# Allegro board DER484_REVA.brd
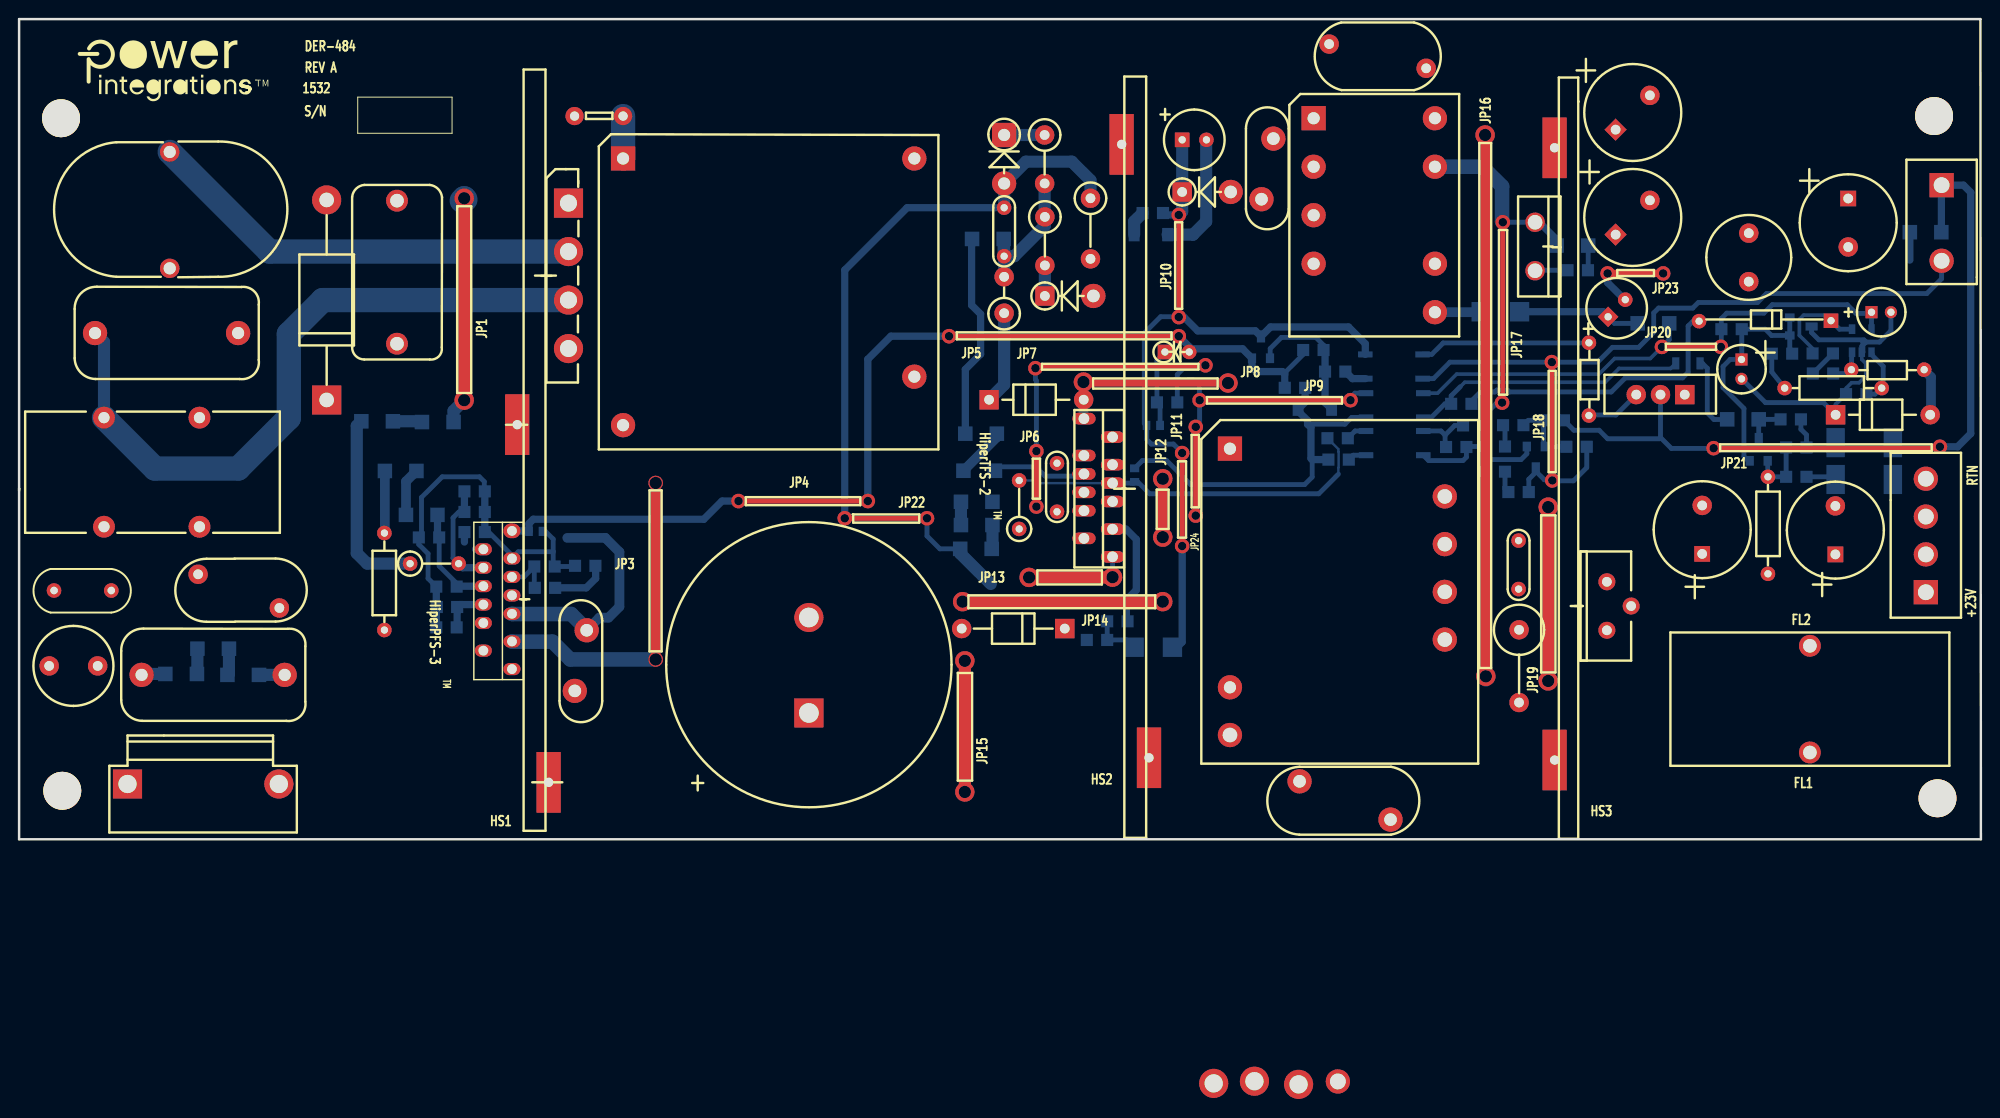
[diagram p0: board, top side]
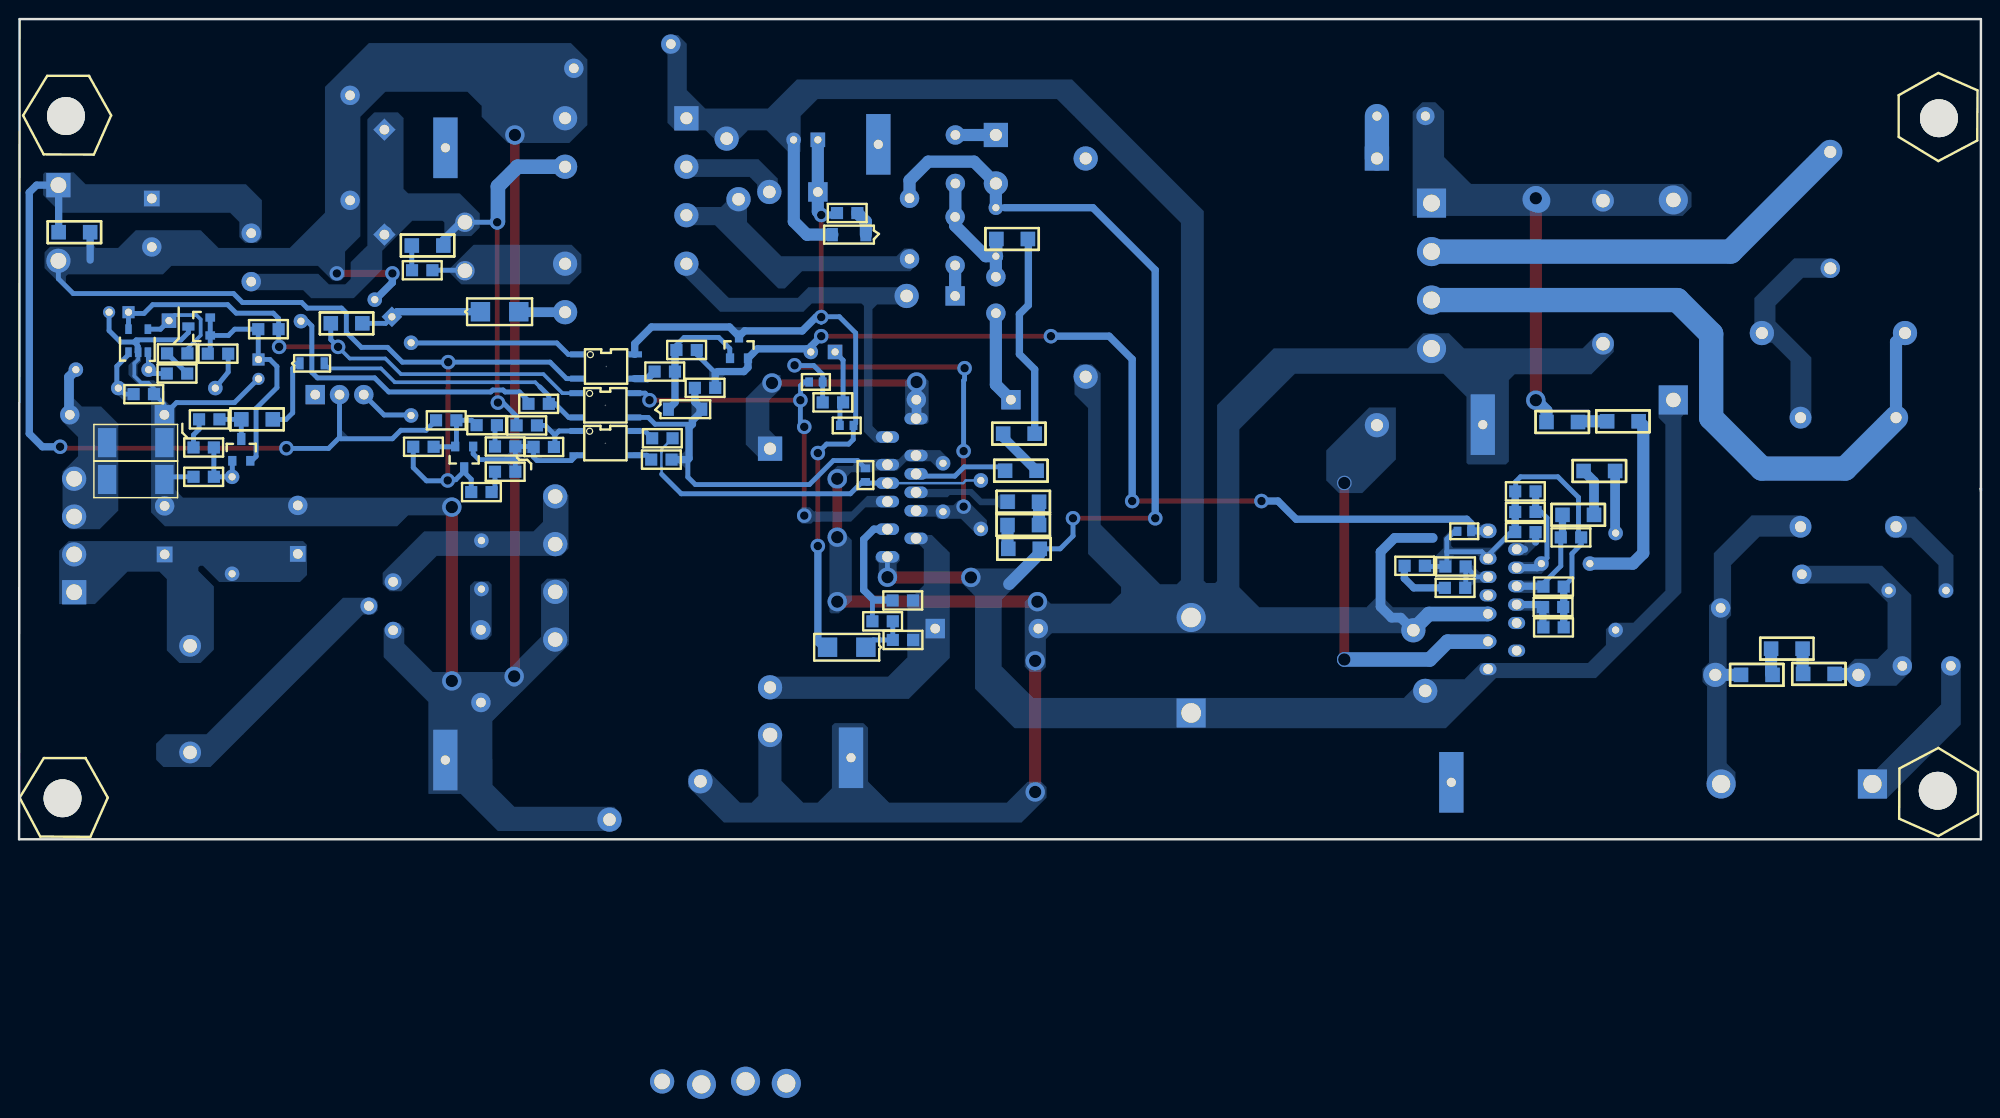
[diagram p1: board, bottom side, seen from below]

Outline 205.44 x 85.93 mm; copper layers: TOP, BOTTOM. Coordinates in mm from the lower left corner of the outline.
Outline path: 0,36.5 0,85.93 205.38,85.93 205.44,0 0,0 0,36.73 0.03,36.73

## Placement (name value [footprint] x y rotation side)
BR1  GBU8K-BP  [PIDAXBRIDGEGBU8]  57.53 66.65 270 top
C1  330 nF  [PINPCAPRAD760X380590050]  12.83 17.22 0 top
C2  330 nF  [PINPCAPRAD760X380590050]  7.95 53.04 0 top
C3  1.0 uF  [PI_NP_CAP_RAD715X370LS590D050]  39.57 66.9 270 top
C4  1 uF  [PISMC0603]  53.39 32.26 0 bottom
C5  1 uF  [PISMC0805]  46.63 32.18 0 bottom
C6  470 pF  [PISMC0805]  46.63 34.29 0 bottom
C7  100 nF  [PISMC0805]  53.95 28.58 0 bottom
C8  1 uF  [PISMC0805]  60.35 28.65 180 bottom
C9  1 nF  [PISMC0805]  45.82 22.2 180 bottom
C10  10 nF  [PINPCAPRAD500X180250040]  58.17 15.54 90 top
C11  470 pF  [PISMC0805]  45.82 26.47 180 bottom
C12  220 uF  [PI_POLCAP_CLY_1181LS400D081]  82.7 13.23 90 top
C13  10 nf  [PISMC0805]  134.67 47.29 180 bottom
C14  2.2 nF  [PINPCAPRAD200X100200030]  103.15 61.09 90 top
C15  100 nF  [PISMC0805]  113.97 25.02 180 bottom
C16  100 nF  [PISMC0805]  113.94 20.88 180 bottom
C17  1.0  uF  [PINPCAPRAD200X100200030]  108.69 34.32 90 top
C18  220pF  [PISMC0603]  116.81 37.44 90 bottom
C19  220 pF  [PINPCAPRAD250X100200030]  157.02 31.29 270 top
C20  150 uF  [PIPOLCAPCYLD400LS200040]  190.2 29.85 90 top
C21  150 uF  [PIPOLCAPCYLD400LS200040]  176.25 29.9 90 top
C22  470 nF  [PISMC0805]  187.17 41.05 180 bottom
C23  10 uF  [PIPOLCAPCLYD200LS80030]  180.37 50.27 270 top
C24  68 nF  [PISMC0805]  187.83 48.79 0 bottom
C25  10 uF  [PIPOLCAPCLYD200LS80030]  193.98 55.22 0 bottom
C26  4.7 nF  [PINPCAPRAD640X260375040]  134.09 6.1 0 top
C27  10 nF  [PINPCAPRAD500X180250040]  131.37 73.41 270 top
C28  100 uF  [PIPOLCAPCYLD250LS100030]  121.79 73.28 0 top
C29  1 nF  [PINPYCAPRAD540X290LS400040]  137.19 83.31 0 top
C30  2.2 nF  [PISMC0805]  162.15 59.61 0 bottom
C31  100 uF  [PIPOLCAPCYLD250LS100030]  166.4 54.74 45 top
C32  1200 uF  [PIPOLCAPCYLD400LS200040]  167.18 74.35 45 top
C33  1200 uF  [PIPOLCAPCYLD400LS200040]  167.18 63.35 45 top
C34  2.2 uF  [PISMC0805]  155.6 38.51 180 bottom
C35  330 nF  [PISMC0805]  155.4 43.38 0 bottom
C36  330 uF  [PIPOLCAPCYLD400LS200040]  191.54 67.13 270 top
C37  1 uF  [PISMC1206]  201.29 63.6 180 bottom
D1  1N5408-T  [PIDV300X200X060DO15D0201AD]  32.21 46.02 90 top
D2  1N4148  [PIDAX375X070030DO35#2]  119.99 51.05 0 top
D3  1N4007  [PIDV200X110X040DO41]  107.42 56.92 0 top
D4  1N4007  [PIDAX475X125040DO41]  101.57 46.05 0 top
D5  US1J  [PISMDSMA]  116.76 20.12 0 bottom
D6  UF4005  [PIDAX475X125040DO41#2]  109.5 22.07 180 top
D7  UF4003  [PIDV200X110X040DO41]  121.79 67.82 0 top
D8  STTH2003CT  [PIDVTO2203]  166.27 24.43 90 top
D9  BAV19WS  [PISMSOD323]  176.02 49.86 180 bottom
D10  1N4148  [PIDAX375X070030DO35]  186.39 54.48 180 top
D11  1N4002-E3/54  [PIDV200X110X040DO41#2]  190.22 44.48 0 top
D12  MBR1045  [PIDVT0220ACREVA]  158.75 59.56 90 top
D13  US1J  [PISMDSMA]  157.12 55.27 180 bottom
F1  5 A  [PI_TR5_SUBMIN_FUSE]  3.15 18.16 0 top
HS1  HEATSINK, W/ ZIERICK, PI CUST  [PI_HS_DER484_BRIDGE]  55.12 80.65 0 top
HS2  HEATSINK, W/ ZIERICK, PI CUST  [PI_HS_DER484_ESIP]  115.75 79.91 270 top
HS3  HEATSINK, W/ ZIERICK, PI CUST  [PI_HS_DER484_DIODES]  161.06 0.05 90 top
J1  CON5  [PI_HDR_5PIN]  11.35 5.79 270 top
J2  CON4  [PI_HDR_4PIN]  199.67 25.88 0 top
J3  CON3  [PI_HDR_3PIN]  201.32 68.53 180 top
JP2  J  [PI_JUMPER200]  58.17 75.77 0 top
L1  9 mH  [PI_IND_4P_500X1050LS450D46_R1]  8.89 32.74 90 top
L2  330 uH  [PI_TOROID_2P_550X950_LS480_D050]  15.77 59.82 90 top
L3  221 uH  [PI_BOBBIN_BPQ32_20_DER484]  63.25 71.32 0 top
L4  880 uH  [PI_IND_2P_TOROIDAL]  187.53 14.68 90 top
L5  2.2 Uh  [PI_CHOKE_COILCRAFT_RFB0807]  181.13 58.42 90 top
NOREF  -  []  -181.41 -162.18 0 top
NOREF#2  -  []  -103.59 36.84 0 top
NOREF#3  -  []  205.44 0 90 top
NOREF#4  -  []  6.15 83.74 0 top
NOREF#5  -  []  0.03 0.03 0 top
POST1  Post Hex, 6-32, snap, 0.375L, NYL  [PIMTGHOLED156]  4.52 5.08 270 bottom
POST2  Post Hex, 6-32, snap, 0.375L, NYL  [PIMTGHOLED156]  200.53 75.77 180 bottom
POST3  Post Hex, 6-32, snap, 0.375L, NYL  [PIMTGHOLED156]  200.89 4.29 180 bottom
POST4  Post Hex, 6-32, snap, 0.375L, NYL  [PIMTGHOLED156]  4.39 75.54 90 bottom
Q1  MMBT4401LT1G  [PISMSOT23123_1]  129.11 50.39 180 bottom
Q2  MMBT4401LT1G  [PISMSOT23123_1]  181.23 39.65 180 bottom
R1  680 k  [PISMR1206]  15.32 17.32 0 bottom
R2  680 k  [PISMR1206]  18.67 19.96 0 bottom
R3  680 k  [PISMR1206]  21.82 17.22 0 bottom
R4  6.2 M  [PISMR1206]  45.49 43.71 180 bottom
R5  6.2 M  [PISMR1206]  39.14 43.79 180 bottom
R6  3.74 M  [PI14WVRESD100LS100D030#2]  40.94 28.88 0 top
R7  162 k  [PISMR0805]  46.63 36.45 0 bottom
R8  30.1 k  [PISMR0805]  54 26.34 0 bottom
R9  332 k  [PISMR0805]  45.87 24.33 180 bottom
R10  3.74 M  [PI14WVRESD100LS100D030]  38.25 21.92 90 top
R11  6.2 M  [PISMR1206]  38.3 38.58 0 bottom
R12  6.2 M  [PISMR1206]  40.51 33.99 0 bottom
R13  162 k  [PISMR0805]  43.99 31.62 180 bottom
R14  4.7 k  [PISMR0805]  136.75 49 0 bottom
R15  4.7 k  [PISMR0805]  134.47 51.26 0 bottom
R16  7.5 k  [PISMR0603]  119.48 43.36 180 bottom
R17  1.33 M  [PISMR1206]  103.1 62.89 180 bottom
R18  1.33 M  [PISMR1206]  99.09 42.49 0 bottom
R19  620  [PISMR0805]  121.29 45.77 180 bottom
R20  1.33 M  [PISMR1206]  102.18 38.61 180 bottom
R21  232 k  [PISMR0603]  121.29 47.9 0 bottom
R22  1.33 M  [PISMR1206]  101.85 30.43 180 bottom
R23  1.33 M  [PISMR1206]  101.93 32.92 180 bottom
R24  1.33 M  [PISMR1206]  101.93 35.36 180 bottom
R25  100  [PI12WVRESD180LS150D040#2]  107.39 73.79 270 top
R26  4.7  [PI12WVRESD180LS150D040#2]  107.42 65.2 270 top
R27  2.2  [PI12WVRESD180LS150D040]  103.15 58.93 270 top
R28  2 k  [PISMR0805]  116.08 22.83 180 bottom
R29  107 k  [PI14WVRESD100LS200D030]  104.72 32.51 90 top
R30  0.0  [PISMR0805]  137.01 42.01 0 bottom
R31  0.0  [PISMR0805]  139.24 39.78 180 bottom
R32  15  [PI2WVRESD200LS300D040]  157.07 21.95 270 top
R33  2.2 k  [PISMR0805]  149.96 45.62 0 bottom
R34  3.3 k  [PISMR0805]  187.81 50.9 0 bottom
R35  1.5 k  [PISMR1206]  182.17 43.99 180 bottom
R36  3.3 k  [PISMR0805]  178.26 53.44 0 bottom
R37  97.6 k  [PISMR0805]  185.67 50.88 180 bottom
R38  1.1 k  [PI14WRESD100LS400D030]  184.89 47.27 0 top
R39  10.2 k  [PISMR0805]  193.45 46.63 180 bottom
R40  100  [PISMR0805]  184.45 43.99 0 bottom
R41  93.1 k  [PI14WRESD100LS400D030]  183.13 37.97 270 top
R42  4.99 k  [PISMR0805]  185.04 37.97 0 bottom
R43  10 k  [PI18WRESD080LS300D030]  191.87 49.2 0 top
R44  0.1  [PISMR2512]  190.22 37.69 0 bottom
R45  220  [PISMR1206]  169.49 54.05 0 bottom
R46  0.1  [PISMR2512]  190.22 41.55 0 bottom
R47  2.2  [PI12WVRESD180LS150D040#3]  112.19 67.16 270 top
R48  1 k  [PISMR0805]  117.65 65.61 0 bottom
R49  10  [PISMR1206]  161.01 62.2 0 bottom
R50  1 k  [PISMR0805]  149.43 41.1 0 bottom
R51  680  [PISMR0805]  155.96 36.37 0 bottom
R52  100  [PISMR0805]  151.21 43.36 0 bottom
R53  1 k  [PISMR0805]  153.47 41.15 0 bottom
R54  4.99 k  [PISMR0805]  161.77 43.89 180 bottom
R55  4.99 k  [PISMR0805]  162.03 41.12 0 bottom
R56  4.7 k  [PI18WVRESD80LS100D030]  164.39 44.4 90 top
RT1  2.5  [PI_RAD180X395LS235D031]  9.65 26.06 180 top
RV1  320 Vac  [PIDISC500X225LS335X140040]  18.75 27.76 0 top
SW1  SPDT SLIDE  [PI_SWITCH_SPDT_SLIDE_PCBM_1]  174.42 46.58 90 top
T1  EER35  [PI_BOBBIN_EER35_14P_DER484]  126.8 40.92 0 top
T2  EF25  [PI_BOBBIN_EF25_10P_DER484]  135.56 75.54 0 top
U1  PFS7528H  [PI_IC_EESIP_SOCKET]  51.61 32.31 270 top
U2  PC357A  [PI_4_SMD]  143.97 49.53 270 bottom
U3  TFS-7706H  [PI_IC_ESIP16-12_OVAL_SLOT_RECPT]  114.5 44.07 270 top
U4  PC357A  [PI_4_SMD]  144.04 45.47 270 bottom
U5  LM431BIM3/NOPB  [PISMSOT23123]  185.42 54.66 90 bottom
U6  LM321  [PISMSOT235]  193.98 51.03 180 bottom
U7  PC357A  [PI_4_SMD]  144.04 41.5 270 bottom
U8  LM431AIM3  [PISMSOT23123]  159.77 41.15 0 bottom
VR1  P6KE150A  [PIDV200X140X050DO15DO204AC]  103.15 73.79 270 top
VR2  MMSZ5243BT1G  [PI_SM_SOD-123_12]  137.44 45.06 180 bottom
VR3  MMSZ5248B-7-F  [PI_SM_SOD-123_12]  116.76 63.35 0 bottom

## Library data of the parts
BR1 = DISCRETE BRIDGE_+~~-: alternate symbols: (pidaxbridgegbu8_horz)
C1-C11 C13-C19 C22 C24 C26 C27 C30 C34 C35 C37 = CAP NP
C12 C20 C21 C32 C33 = CAP POL
C23 C25 = CAP POL: alternate symbols: (pipolcapclyd200ls80030h)
C28 = CAP POL: alternate symbols: (pipolcapclyd250ls100d30h590); tolerance: 20
C29 = CAP NP: alternate symbols: (pinpycaprad540x290ls400040h)
C31 = CAP POL: alternate symbols: (pipolcapclyd250ls100d30h590)
C36 = CAP POL: alternate symbols: (pipolcapclyd400x530ls200030h)
D1 = DIODE: alternate symbols: (pidax800x225060do15do201ad,pidv300x200x060do14wbead)
D2 D10 = DIODE: alternate symbols: (pidax375x070030do35,pidv100x080x030do35)
D3 D4 D7 D11 = DIODE: alternate symbols: (pidax475x125040do41,pidv200x110x040do41wbead,pidax390x125040do41)
D5 D9 D13 = DIODE
D6 = DIODE: alternate symbols: (pidax475x125040do41,pidax390x125040do41)
D8 = D_DUAL_CK_ACA_4: alternate symbols: (pidvto2203vf1)
D12 = DIODE SCHOTTKY
F1 = FUSE
HS1-HS3 = HS-PI_CUSTOM2
J1 = CON5
J2 = CON4
J3 = CON3
JP2 = JUMPER_1
L1 = INDUCTOR_4P_revB: alternate symbols: (pi_ind_4p_500x1050ls450d46_r1)
L2 L5 = INDUCTOR
L3 = INDUCTOR_DER484_PFC
L4 = INDUCTOR_DER484
POST1-POST4 = POST_CRKT_BRD_6-32_HEX
Q1 Q2 = NPN_BEC
R1-R5 R7-R9 R11-R22 R28 R30 R31 R33-R37 R39 R40 R42 R44-R46 R48-R55 = R
R6 R10 R29 R38 R41 = R: alternate symbols: (pi14wvresd100ls200d030,pi14wresd100ls400d030,pi14wresd100ls500d030)
R23 R24 = R: tolerance: 1%
R25-R27 R47 = R: alternate symbols: (pi12wvresd180ls200d040,pi12wvresd180ls250d040,pi12wresd180ls675d040)
R32 = R: alternate symbols: (pi2wresd200ls900d040,pi2wvresd200ls300d040,pi2wvresd200ls400d040)
R43 = R: alternate symbols: (pi18wresd080ls300d030); tolerance: 1%
R56 = R: alternate symbols: (pi18wresd080ls300d030)
RT1 = THERMISTOR: alternate symbols: (pirad550x410ls300040_h)
RV1 = VARISTOR: alternate symbols: (pi_rad450x550ls300d040_h)
SW1 = SW SLIDE-SPDT
T1 = BEER35_CUSTOM_DER484
T2 = BEF25_CUSTOM_DER484
U1 = DEV_HIPERPFS-3-eSIP-16C: alternate symbols: (pi_ic_esip16-13_socket_hpii ,pi_ic_esip16-13_oval_hpii,pi_ic_eesip_socket)
U2 U4 U7 = OPTO_A_B
U3 = HiperTFS_II_I_2_ROW: alternate symbols: (pi_ic_esip16-12_oval_slot_recpt)
U5 U8 = TL431/SOT-23_CAR
U6 = LM321_SOT23-5
VR1 = DIODE_ZENER: alternate symbols: (pidax550x140050do15do204ac)
VR2 VR3 = DIODE_ZENER

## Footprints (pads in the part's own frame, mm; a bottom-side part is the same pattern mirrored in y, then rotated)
PI2WVRESD200LS300D040
  round 2.032 hole 1.016: 1(0,0) 2(7.62,0)
PI12WVRESD180LS150D040
  round 2.032 hole 1.016: 1(0,0) 2(3.81,0)
PI12WVRESD180LS150D040#2
  round 2.032 hole 1.016: 1(0,0) 2(5.08,0)
PI12WVRESD180LS150D040#3
  round 2.032 hole 1.016: 1(0,0) 2(6.35,0)
PI14WRESD100LS400D030
  round 1.524 hole 0.762: 1(0,0) 2(10.16,0)
PI14WVRESD100LS100D030
  round 1.524 hole 0.762: 1(0,0) 2(10.16,0)
PI14WVRESD100LS100D030#2
  round 1.524 hole 0.762: 1(0,0) 2(5.08,0)
PI14WVRESD100LS200D030
  round 1.524 hole 0.762: 1(0,0) 2(5.08,0)
PI18WRESD080LS300D030
  round 1.524 hole 0.762: 1(0,0) 2(7.62,0)
PI18WVRESD80LS100D030
  round 1.524 hole 0.762: 1(0,0) 2(7.62,0)
PI_4_SMD
  rect 0.635x1.524 smd: 1(-1.27,-2.997) 2(1.27,-2.997) 3(1.27,2.997) 4(-1.27,2.997)
PI_BOBBIN_BPQ32_20_DER484
  round 2.54 hole 1.27: (30.5,0) 6(0,-27.94) 8(30.5,-22.86)
  rect 2.54x2.54 hole 1.27: 1(0,0)
PI_BOBBIN_EER35_14P_DER484
  rect 2.54x2.54 hole 1.27: 1(0,0)
  round 2.54 hole 1.27: 6(0,-25.001)
  round 2.54 hole 1.524: 7(0,-30) 10(22.499,-20) 11(22.499,-15.001) 12(22.499,-10) 13(22.499,-5.001)
PI_BOBBIN_EF25_10P_DER484
  rect 2.54x2.54 hole 1.27: 1(0,0)
  round 2.54 hole 1.27: 2(0,-5.08) 3(0,-10.16) 4(0,-15.24) 6(12.7,-20.32) 7(12.7,-15.24) 9(12.7,-5.08) 10(12.7,0)
PI_CHOKE_COILCRAFT_RFB0807
  round 2.032 hole 1.016: 1(0,0) 2(5.08,0)
PI_HDR_3PIN
  rect 2.54x2.54 hole 1.651: 1(0,0)
  round 2.54 hole 1.651: 2(63.221,93.904) 3(0,7.925)
PI_HDR_4PIN
  rect 2.54x2.54 hole 1.651: 1(0,0)
  round 2.54 hole 1.651: 2(0,3.962) 3(0,7.925) 4(0,11.887)
PI_HDR_5PIN
  rect 3.048x3.048 hole 1.905: 1(0,0)
  round 3.048 hole 1.905: 2(31.369,113.741) 3(31.14,118.008) 4(31.471,122.631) 5(0,15.85)
PI_HS_DER484_BRIDGE
  rect 2.54x6.35 hole 0.965: 1(-2.957,-37.208) 2(0.338,-74.681)
PI_HS_DER484_DIODES
  rect 6.35x2.54 hole 0.965: 1(8.247,0.259) 2(72.393,0.272)
PI_HS_DER484_ESIP
  rect 6.35x2.54 hole 0.965: 1(71.369,2.57) 2(7.104,-0.287)
PI_IC_EESIP_SOCKET
  oval 1.524x1.778 hole 1.016: 1(0,0)
  oval 1.27x1.778 hole 1.016: 3(1.93,-2.997) 4(2.896,0) 5(3.861,-2.997) 6(4.826,0) 7(5.791,-2.997) 8(6.756,0) 9(7.722,-2.997) 10(8.687,0) 11(9.652,-2.997) 13(11.582,0) 14(12.548,-2.997) 16(14.478,0)
PI_IC_ESIP16-12_OVAL_SLOT_RECPT
  oval 1.219x2.438 hole 1.118: 1(0,-2.997) 3(1.93,0) 5(3.861,-2.997) 6(4.826,0) 7(5.791,-2.997) 8(6.756,0) 9(7.722,-2.997) 10(8.687,0) 11(9.652,-2.997) 13(11.582,0) 14(12.548,-2.997) 16(14.478,0)
PI_IND_2P_TOROIDAL
  round 2.286 hole 1.422: 1(-5.588,0) 2(5.588,0)
PI_IND_4P_500X1050LS450D46_R1
  round 2.286 hole 1.168: 1(0,-10) 2(11.43,-10) 3(0,0) 4(11.43,0)
PI_JUMPER200
  round 1.905 hole 0.965: 1(0,0) 2(5.08,0)
PI_NP_CAP_RAD715X370LS590D050
  round 2.286 hole 1.422: 1(0,0) 2(14.986,0)
PI_POLCAP_CLY_1181LS400D081
  rect 3.048x3.048 hole 2.057: 1(0,0)
  round 3.048 hole 2.057: 2(10,0)
PI_RAD180X395LS235D031
  round 1.524 hole 0.787: 1(0,0) 2(5.994,0)
PI_SM_SOD-123_12
  rect 1.143x1.397 smd: 1(0,0) 2(3.505,0)
PI_SWITCH_SPDT_SLIDE_PCBM_1
  rect 2.032x2.032 hole 1.016: 1(0,0)
  round 2.032 hole 1.016: 2(0,2.54) 3(0,5.08)
PI_TOROID_2P_550X950_LS480_D050
  round 2.032 hole 1.27: 1(0,0) 2(12.192,0)
PI_TR5_SUBMIN_FUSE
  round 2.032 hole 1.016: 1(0,0) 2(5.08,0)
PIDAX375X070030DO35
  rect 1.524x1.524 hole 0.762: 1(-3.353,0.152)
  round 1.524 hole 0.762: 2(10.465,0.203)
PIDAX375X070030DO35#2
  rect 1.524x1.524 hole 0.762: 1(0,0)
  round 1.524 hole 0.762: 2(2.54,0)
PIDAX475X125040DO41
  rect 2.032x2.032 hole 1.016: 1(0,0)
  round 2.032 hole 1.016: 2(9.906,0)
PIDAX475X125040DO41#2
  rect 2.032x2.032 hole 1.016: 1(0,0)
  round 2.032 hole 1.016: 2(10.795,0)
PIDAXBRIDGEGBU8
  rect 3.048x3.048 hole 1.778: 1(0,0)
  round 3.048 hole 1.778: 2(5.08,0) 3(10.16,0) 4(15.24,0)
PIDISC500X225LS335X140040
  round 2.032 hole 1.016: 1(0,0) 2(8.509,-3.531)
PIDV200X110X040DO41
  rect 2.032x2.032 hole 1.016: 1(0,0)
  round 2.54 hole 1.321: 2(5.08,0)
PIDV200X110X040DO41#2
  rect 2.032x2.032 hole 1.016: 1(0,0)
  round 2.032 hole 1.016: 2(9.906,0)
PIDV200X140X050DO15DO204AC
  rect 2.54x2.54 hole 1.27: 1(0,0)
  round 2.54 hole 1.27: 2(5.08,0)
PIDV300X200X060DO15D0201AD
  rect 3.048x3.048 hole 1.524: 1(0,0)
  round 3.048 hole 1.524: 2(20.955,0)
PIDVT0220ACREVA
  round 2.032 hole 1.524: 1(5.08,0) 2(0,0)
PIDVTO2203
  round 1.778 hole 1.016: 1(-2.54,0) 2(0,-2.54) 3(2.54,0)
PIMTGHOLED156
  round 3.962 hole 3.962: 1(0,0)
PINPCAPRAD200X100200030
  round 1.524 hole 0.762: 1(0,0) 2(5.08,0)
PINPCAPRAD250X100200030
  round 1.524 hole 0.762: 1(0,0) 2(5.08,0)
PINPCAPRAD500X180250040
  round 2.54 hole 1.321: 1(0,-0.025) 2(6.35,-1.27)
PINPCAPRAD640X260375040
  round 2.54 hole 1.321: 1(0,-0.025) 2(9.525,-4.039)
PINPCAPRAD760X380590050
  round 2.54 hole 1.27: 1(0,0) 2(14.986,0)
PINPYCAPRAD540X290LS400040
  round 2.032 hole 1.016: 1(0,0) 2(10.16,-2.54)
PIPOLCAPCLYD200LS80030
  rect 1.27x1.27 hole 0.762: 1(0,0)
  round 1.27 hole 0.762: 2(2.032,0)
PIPOLCAPCYLD250LS100030
  rect 1.524x1.524 hole 0.762: 1(0,0)
  round 1.524 hole 0.762: 2(2.54,0)
PIPOLCAPCYLD400LS200040
  rect 1.651x1.651 hole 1.016: 1(0,0)
  round 2.032 hole 1.016: 2(5.08,0)
PISMC0603
  rect 0.813x0.965 smd: 1(0,0) 2(1.422,0)
PISMC0805
  rect 1.27x1.27 smd: 1(0,0) 2(2.134,0)
PISMC1206
  rect 1.524x1.524 smd: 1(0,0) 2(3.302,0)
PISMDSMA
  rect 2.032x2.032 smd: 1(0,0) 2(4.013,0)
PISMR0603
  rect 0.813x0.965 smd: 1(0,0) 2(1.422,0)
PISMR0805
  rect 1.27x1.27 smd: 1(0,0) 2(2.134,0)
PISMR1206
  rect 1.524x1.524 smd: 1(0,0) 2(3.302,0)
PISMR2512
  rect 1.93x3.048 smd: 1(0,0) 2(5.994,0)
PISMSOD323
  rect 0.762x1.27 smd: 1(0,0) 2(2.54,0)
PISMSOT235
  rect 0.686x1.016 smd: 1(0,0) 2(1.016,0) 3(2.032,0) 4(2.032,2.413) 5(0,2.413)
PISMSOT23123
  rect 0.864x1.016 smd: 1(-1.88,0) 3(0,0)
  rect 0.864x1.27 smd: 2(-0.94,2.286)
PISMSOT23123_1
  rect 0.864x1.016 smd: 1(-1.88,0) 2(0,0)
  rect 0.864x1.27 smd: 3(-0.94,2.286)

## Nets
+5VS: C36.1 C37.1 J3.1 L5.2 R54.1 SW1.2
VCCPR: C4.1 C13.2 D2.2 Q1.2(EMITTER) R15.1 U1.1(VCC)
B+: C10.1 C12.1 C14.2 D1.1 R10.1 R22.2 R47.1 U1.16(K) U3.16(HD) VR1.2
RTN: BR1.4(-DC) C3.2 C10.2 C12.2 C13.1 C17.2 C18.2 C26.1 C27.1 C28.2 C29.1 D6.2 HS1.1 HS2.1 L3.8 R31.2 T1.7 T2.1 U1.10(S1) U3.5(G) U3.6(S) U4.3(E) VR2.2 VR3.2
SOURCE: U1.11
VRECT: BR1.1(+DC) C3.1 D1.2 JP2.1 R4.1
N8573798: C20.2 C21.2 C23.2 C25.2 C26.2 C29.2 C31.2 C32.2 C33.2 C36.2 C37.2 D8.1(A1) D11.1 HS3.1 J3.3 R32.2 R39.2 R42.2 R44.1 R46.1 R51.2 R55.2 T1.10 T1.11 T2.10 U2.2(C) U5.2(A) U6.2(V-) U8.2(A)
N8573822: D8.2(CATHODE) L4.1
N8573908: C15.2 C16.2 D6.1 T1.6 U3.14(HS)
N8573924: C14.1 R17.1 R25.2 R26.1 R27.1
N8573984: C23.1 Q2.2(EMITTER) R36.2 R37.1 U5.1(C) U5.3(VREF)
N8573988: C15.1 R28.1 U3.13(VDDH)
N8574066: R23.2 R24.2
N8574082: D4.2 T1.1 U3.1(D)
N8574090: C17.1 R19.1 R21.1 R29.1 U3.11(BP)
N8574122: D11.2 J2.3 J2.4 R43.2 R44.2 R46.2
N8574162: C18.1 R29.2 R30.1 U3.8(EN)
N8574170: C19.1 D8.3(A2) T1.12 T1.13
N8574254: R20.1 U3.7(R)
N8574324: R24.1 U3.9(L)
N8574348: C20.1 C21.1 J2.1 J2.2 L4.2 R41.2
N8574438: R21.2 U3.10(FB) U4.4(C)
N8574464: C25.1 R36.1 R45.2 U4.1(A) U6.5(V+)
N8574666: C32.1 C33.1 D12.1 L5.1 R49.1 R52.2 T2.9
N8574858: C28.1 D5.2 D7.1 Q1.3(COLLECTOR) R16.2 R48.2 U2.4(C)
N8574878: C27.2 R47.2 T2.3
N8574990: D3.2 T2.4 U3.3(DSB)
N8575976: C19.2 R32.1
N8576150: R38.2 R39.1 U6.1(+IN)
N8576178: D10.1 R34.1 U6.4(OUT)
N8576798: R18.2 R20.2
N8576938: R50.1 R52.1 U7.1(A)
N8576942: C34.2 R50.2 R53.1 U7.2(C) U8.1(C)
N8577402: C35.2 R54.2 R55.1 U8.3(VREF)
N8577904: R17.2 R18.1
N8578122: R22.1 R23.1
N8582199: Q1.1(BASE) R14.1 R15.2 VR2.1
N8582213: D2.1 R16.1 R19.2
N8613531: C24.2 R43.1 U6.3(-IN)
N8617835: C34.1 R51.1
N8621032: C4.2 C5.2 C6.2 C7.2 C8.2 C9.2 C11.2 R7.2 R9.2 R13.2 U1.4(G)
N8621040: C9.1 R9.1 U1.9(PGT)
N8621064: C8.1 R8.2
N8621068: C7.1 R8.1 U1.6(C)
N8621110: C6.1 R6.2 R7.1 U1.5(V)
N8621154: C5.1 U1.3(REF)
N8621242: JP2.2 L3.1
N8621246: C1.2 J1.5 L1.1 R3.2 RV1.2
N8621358: C2.2 L1.2 L2.1
N8621428: BR1.2(AC1) L2.2
N8621454: R1.2 R2.1
N8621482: C1.1 F1.2 R1.1 RT1.1 RV1.1
N8621528: F1.1 J1.1
N8621724: BR1.3(AC2) C2.1 L1.4
N8621808: R4.2 R5.1
N8621812: R5.2 R6.1
N8622000: L1.3 RT1.2
N8622846: C11.1 R12.2 R13.1 U1.7(FB)
N8622966: R10.2 R11.1
N8622970: R11.2 R12.1
N8625218: R2.2 R3.1
N8628411: R25.1 VR1.1
N8629085: R30.2 U7.4(C)
N8629124: D4.1 R27.2
N8637240: C35.1 R53.2
N8639668: D3.1 R26.2
N8650505: R14.2 U2.3(E)
N8659234: R56.1 SW1.3
N8659238: R56.2 U2.1(A)
N8678796: C16.1 D5.1 R28.2
N8704340: C22.2 Q2.1(BASE) R41.1 R42.1
N8715929: Q2.3(COLLECTOR) R35.1 R40.1
N8730428: D9.2 R33.1 U4.2(C)
N8731215: D9.1 R35.2
N8736247: C31.1 D13.1 R45.1
N8746626: C30.1 D12.2 T2.7
N8749328: D10.2 R33.2
N8758678: R37.2 R38.1
N8762816: R31.1 U7.3(E)
N8800122: D13.2 T2.6
N8801044: C30.2 R49.2
N8805084: D7.2 T2.2
N8807537: R48.1 VR3.1
N8808690: L3.6 U1.13(D)
N85759681: C24.1 R34.2
N87060550: C22.1 R40.2

Pads without a net: HS1 2; HS2 2; HS3 2; J1 2 3 4; J3 2; POST1 1; POST2 1; POST3 1; POST4 1; SW1 1; U1 8 14

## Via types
v1: diameter 1.524, hole 0.889, TOP to BOTTOM, 28 vias
v2: diameter 2.032, hole 1.295, TOP to BOTTOM, 16 vias
v3: diameter 1.524, hole 1.295, TOP to BOTTOM, 2 vias

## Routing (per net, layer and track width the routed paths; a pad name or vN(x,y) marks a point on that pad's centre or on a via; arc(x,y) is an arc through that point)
+5VS: length 82.6
  TOP w0.508: v1(201.14,41.12) 200.99,40.97 v1(177.44,40.97)
  BOTTOM w0.508: R54.1 162.81,42.85 165.46,42.85 166.34,41.96 171.75,41.96 171.88,42.09 ; SW1.2 171.88,42.09 ; 171.88,42.09 173.02,40.94 177.42,40.94 v1(177.44,40.97)
  BOTTOM w0.762: J3.1 203.61,68.53 204.37,67.77 204.37,42.49 203,41.12 v1(201.14,41.12) ; C37.1 201.29,68.5
  BOTTOM w1.524: J3.1 201.29,68.5
VCCPR: length 106.2
  TOP w0.508: v1(75.34,35.43) v1(88.87,35.43) ; v1(121.44,52.7) v1(97.38,52.7)
  BOTTOM w0.508: 132.28,49 132.66,49 134.47,50.8 R15.1
  BOTTOM w0.762: v1(75.34,35.43) 73.61,35.43 71.7,33.53 53.85,33.53 53.39,33.07 C4.1 53.34,32.31 U1.1 ; v1(88.87,35.43) 88.87,50.29 91.29,52.7 v1(97.38,52.7) ; C13.2 132.54,48.74 132.28,49 129.54,49 129.11,49.43 Q1.2 128.12,51.38 122.86,51.38 D2.2 122.53,51.61 v1(121.44,52.7)
B+: length 91
  TOP w0.508: v1(86.46,33.63) v1(95.07,33.63)
  TOP w1.27: v2(114.5,27.46) 114.48,27.43 v2(105.77,27.43)
  BOTTOM w0.508: v1(95.07,33.63) 95.07,31.78 96.42,30.43 R22.2 ; 102.23,66.17 C14.2 ; U3.16 v2(114.5,27.46)
  BOTTOM w0.762: v1(86.46,33.63) 86.46,59.64 92.99,66.17 102.23,66.17
  BOTTOM w1.27: 101.75,26.75 98.55,29.95 R22.2 ; C14.2 VR1.2 105.44,70.99 110.24,70.99 112.19,69.04 R47.1
RTN: length 119.5
  TOP w1.016: v2(119.76,37.77) v2(119.76,31.65)
  TOP w1.27: v2(119.76,24.89) v2(98.81,24.89) ; v2(99.03,4.95) v2(99.03,18.69)
  BOTTOM w0.381: 122.91,63.35 124.28,64.72
  BOTTOM w0.508: U4.3 139.55,44.2 138.84,43.48 134.92,43.48 ; C18.2 117.63,39.67 120.17,39.67 122.68,37.16 134.62,37.16 135.41,37.95 135.41,39.78
  BOTTOM w0.762: C13.1 134.67,45.8 VR2.2 133.93,44.86 134.92,43.87 134.92,43.48 135.28,43.13 135.28,39.9 135.41,39.78 R31.2
  BOTTOM w1.016: C10.2 60.76,23.22 61.72,23.22 62.86,24.36 62.86,30.1 61.39,31.57 57.4,31.57
  BOTTOM w1.27: C28.2 124.31,73.25 124.31,64.72 122.94,63.35 VR3.2
  BOTTOM w1.524: C10.2 59.44,21.97 57.81,23.6 51.64,23.6 U1.10
VRECT: length 24.8
  TOP w1.27: v2(46.61,46) v2(46.61,67.16)
  BOTTOM w1.27: v2(46.61,46) 45.49,44.88 R4.1 ; 32.28,66.9 D1.2
  BOTTOM w2.54: BR1.1 57.35,66.83 ; 46.74,67.03 v2(46.61,67.16) 46.35,66.9
N8573798: length 212.7
  TOP w0.508: v1(160.5,49.99) v1(160.55,37.59)
  TOP w0.762: v1(166.34,59.28) v1(172.16,59.28)
  TOP w1.016: v2(153.59,17.07) 153.52,17.14 v2(153.52,73.79)
  TOP w1.27: v2(160.12,34.8) v2(160.12,16.59)
  BOTTOM w0.381: 191.34,46.66 R39.2 190.22,45.54 ; 191.34,46.66 191.32,46.68 191.32,47.25 191.9,47.83 192.67,47.83 193.37,48.53 193.37,49.86 192.96,50.27 U6.2 ; 191.34,46.66 191.29,46.66 190.22,45.59 190.22,45.54 ; 190.22,45.54 D11.1
  BOTTOM w0.508: J3.3 201.32,58.72 199.77,57.18 182.98,57.18 182.04,56.24 175.85,56.24 175.26,55.65 171.68,55.65 171.17,55.14 171.17,53.11 169.6,51.54 166.85,51.54 165.3,49.99 v1(160.5,49.99) 149.83,49.99 148.11,48.26 U2.2 ; C23.2 180.39,48.23 182.88,45.75 188.95,45.75 D11.1 ; R51.2 158.09,37.72 158.83,38.46 158.83,38.56 ; U5.2 187.71,53.09 188.47,52.32 193.17,52.32 193.4,52.1 ; 193.4,52.1 193.08,52.1 193.08,51.03 U6.2 192.96,51.66 193.4,52.1 ; 193.4,52.1 194.82,52.1 196.01,53.29 C25.2 ; U8.2 158.83,38.56 ; 158.83,38.56 159.72,37.67 160.02,37.67 160.1,37.59 v1(160.55,37.59) 160.59,37.55 162.78,37.55 164.16,38.94 R55.2 ; R44.1 189.94,37.97 R42.2
  BOTTOM w0.762: C31.2 168.13,56.53 166.34,58.32 v1(166.34,59.28) ; 160.05,34.87 v2(160.12,34.8) ; 197.99,60.68 C37.2
  BOTTOM w1.27: v2(153.59,17.07) 153.59,16.62
  BOTTOM w1.524: 148.41,75.51 148.44,75.54 T2.10
N8573924: length 15.8
  BOTTOM w1.27: R27.1 103.15,60.83 103.1,60.88 R17.1 103.15,62.84 C14.1 104.22,61.09 107.42,64.29 R26.1 107.39,65.23 R25.2
N8573984: length 25.7
  BOTTOM w0.508: U5.1 185.42,51.13 R37.1 ; U5.1 U5.3 ; U5.1 183.51,52.78 182.85,53.44 R36.2 180.39,50.29 C23.1 179.17,50.27 178.44,49.53 178.44,47.32 180.62,45.14 180.62,40.11 181.08,39.65 Q2.2
N8573988: length 14
  BOTTOM w0.508: 115.95,25.07 116.08,24.94 R28.1
  BOTTOM w0.762: U3.13 115.93,32.49 116.99,31.42 116.99,26.11 115.95,25.07 114.02,25.07 C15.1
N8574066: length 5
  BOTTOM w1.016: R23.2 98.7,32.99 98.7,35.41
  BOTTOM w1.27: R23.2 R24.2
N8574082: length 19.1
  TOP w0.762: v2(126.59,47.8) 111.86,47.8 111.76,47.9 v2(111.46,47.9)
  BOTTOM w1.016: 111.46,43.97 v2(111.46,47.9)
N8574090: length 38.7
  TOP w0.508: v1(106.43,49.35) 106.55,49.48 124.05,49.48 v1(124.23,49.66) ; v1(106.53,34.85) v1(106.53,40.67)
  BOTTOM w0.508: v1(106.53,40.67) 106.53,48.06 106.43,48.16 v1(106.43,49.35) ; v1(124.23,49.66) 124.21,49.63 122.22,49.63 121.29,48.69 R21.1 R19.1
N8574122: length 5.1
  BOTTOM w1.016: R43.2 199.49,49.15 200.21,48.43 200.21,44.56 ; D11.2 200.21,44.56 ; 200.21,44.56 200.26,44.61
N8574162: length 39.2
  BOTTOM w0.254: 138.15,38.25 138.15,38.94 138.18,38.96 138.18,40.59 138.15,40.62 138.15,40.87 R30.1 ; U3.8 106.58,37.31 106.3,37.59 R29.2
  BOTTOM w0.508: 138.15,38.25 136.09,36.2 118.39,36.2 117.14,37.44 C18.1 116.69,37.31 U3.8
N8574254: length 10
  BOTTOM w0.508: U3.7 111.28,38.05 107.44,38.05 106.48,39.01 102.74,39.01 102.34,38.61 R20.1
N8574348: length 0
  BOTTOM w1.016: 190.17,29.82 C20.1
N8574438: length 32.7
  TOP w0.508: v1(123.62,46) v1(139.42,46) ; v1(123.22,43.21) v1(123.22,33.91)
  BOTTOM w0.508: U4.4 139.88,46.74 139.42,46.28 v1(139.42,46) ; R21.2 123.22,47.9 123.6,47.52 123.6,46.02 v1(123.62,46) 123.62,43.61 v1(123.22,43.21)
N8574464: length 57.5
  TOP w0.508: v1(172.03,51.59) v1(178.21,51.59)
  BOTTOM w0.381: v1(172.03,51.59) 170.81,50.37 167.08,50.37 165.44,48.73 150.53,48.73 148.54,46.74 U4.1
  BOTTOM w0.508: v1(178.21,51.59) 178.26,51.64 R36.1 178.26,54.56 178.82,55.12 182.7,55.12 183.59,56.01 191.44,56.01 192.35,55.09 193.85,55.09 C25.1 U6.5 ; v1(172.03,51.59) 172.8,52.35 R45.2
N8574666: length 40.8
  TOP w0.508: v1(155.37,64.64) 155.37,45.82 v1(155.3,45.75)
  BOTTOM w0.508: D12.1 v1(155.37,64.64) ; v1(155.3,45.75) 154.76,45.75 153.34,44.32 R52.2
  BOTTOM w0.762: 159.18,64.64 161.01,62.81 R49.1
  BOTTOM w1.524: C33.1 167.18,63.4 167.11,63.47 ; v1(155.37,64.64) 155.3,64.72 155.3,68.4 153.24,70.46 T2.9
N8574858: length 85
  TOP w0.508: v1(121.44,65.41) v1(121.44,54.71) ; v1(121.79,30.72) v1(121.79,40.46)
  BOTTOM w0.508: v1(121.79,40.46) 121.79,40.49 120.88,41.4 118.57,41.4 118.08,41.88 118.08,43.33 R16.2 117.83,43.59 117.83,53.04 119.54,54.74 120.87,54.74 121.44,54.18 121.97,54.71
  BOTTOM w0.762: D5.2 121.25,20.12 121.79,20.66 v1(121.79,30.72) ; U2.4 140.97,51.92 139.22,53.67 131.04,53.67 Q1.3 129.46,53.26 123.42,53.26 121.97,54.71 v1(121.44,54.71) ; v1(121.44,65.41) 119.99,65.41 R48.2
  BOTTOM w1.27: C28.1 D7.1 121.79,65.76 v1(121.44,65.41)
N8576150: length 6.2
  BOTTOM w0.508: U6.1 193.98,50.77 195.2,49.56 195.2,47.5 R38.2 194.34,46.63 R39.1
N8576178: length 10.5
  BOTTOM w0.381: R34.1 187.81,51.41 186.42,52.79 186.42,54.47 186.87,54.91 189.15,54.91 D10.1
  BOTTOM w0.508: D10.1 190.63,53.44 U6.4
N8576798: length 5.3
  BOTTOM w1.016: R20.2 102.39,42.11 R18.2
N8576938: length 6.1
  BOTTOM w0.508: 149.33,42.34 149.33,41.2 R50.1 ; 149.33,42.34 150.34,43.36 R52.1 ; 149.33,42.34 148.89,42.77 U7.1
N8576942: length 16
  BOTTOM w0.508: U8.1 157.89,40.39 157.28,39.78 153.62,39.78 153.47,39.93 ; 153.47,39.93 R53.1 151.61,41.15 R50.2 151.56,40.04 151.2,39.67 147.6,39.67 U7.2 ; 153.47,39.93 C34.2
N8577402: length 7.4
  BOTTOM w0.508: R55.1 159.79,41.12 U8.3 159.64,41.27 R54.2 158.04,43.89 C35.2
N8577904: length 21.5
  BOTTOM w0.762: R18.1 99.09,49.23 100.69,50.83 100.69,55.02 99.75,55.96 99.75,62.84 R17.2
N8578122: length 2.5
  BOTTOM w1.27: R23.1 101.93,30.51 R22.1
N8582199: length 14.5
  BOTTOM w0.508: Q1.1 131.01,50.42 131.01,51.41 132.18,52.58 135.79,52.58 136.6,51.77 R15.2
  BOTTOM w0.762: VR2.1 136.75,45.75 R14.1 136.75,51.1 R15.2
N8582213: length 8.2
  BOTTOM w0.508: 119.51,43.33 R16.1 119.48,45.44 R19.2 119.15,50.19 119.99,51.03 D2.1
N8613531: length 3.9
  BOTTOM w0.508: U6.3 191.9,50.98 191.9,49.23 R43.1 191.8,49.2 191.39,48.79 C24.2
N8617835: length 2.3
  BOTTOM w0.508: R51.1 155.6,36.73 C34.1
N8621032: length 42.8
  BOTTOM w0.508: C11.2 42.82,27.33 42.82,29.92 41.86,30.89 R13.2 42.14,31.9 42.14,35.81 44.3,37.97 48.21,37.97 48.72,37.46 48.72,36.5 R7.2 ; 55.93,30.12 52.27,30.12 51.61,29.46 ; 55.93,30.12 55.93,28.73 C7.2 58.14,28.58 C8.2 ; 55.93,30.12 55.93,31.45 55.12,32.26 C4.2 ; 51.61,29.46 U1.4 ; 51.61,29.46 51.61,29.74 49.17,32.18 C5.2
  BOTTOM w0.762: C5.2 C6.2 R7.2 ; C9.2 43.69,24.28 R9.2 43.69,24.38 C11.2
N8621040: length 5
  BOTTOM w0.762: C9.1 45.87,22.25 R9.1 46.13,24.59 U1.9
N8621064: length 6
  BOTTOM w0.762: C8.1 60.38,28.63 60.38,27.33 59.39,26.34 R8.2
N8621068: length 5
  BOTTOM w0.508: U1.6 52.86,27.48 C7.1 53.95,26.39 R8.1
N8621110: length 11.4
  BOTTOM w0.508: C6.1 46.05,34.29 45.44,33.68 45.44,29.46 R6.2
  BOTTOM w0.762: U1.5 46.46,28.45 R6.2 ; R7.1 C6.1
N8621154: length 1.9
  BOTTOM w0.762: 46.63,31.14 C5.1 ; U1.3 47.8,30.38
N8621242: length 4.4
  BOTTOM w2.54: JP2.2 L3.1
N8621246: length 2.7
  BOTTOM w1.27: C1.2 R3.2
N8621428: length 46.1
  BOTTOM w2.54: BR1.2 26.21,61.57 L2.2
N8621454: length 2.7
  BOTTOM w1.27: R2.1 18.67,17.37 R1.2
N8621482: length 2.5
  BOTTOM w1.27: C1.1 12.93,17.32 R1.1
N8621724: length 72.6
  BOTTOM w1.27: L1.4 8.89,52.1 C2.1
  BOTTOM w2.54: BR1.3 31.8,56.49 28.24,52.93 28.24,44.15 22.94,38.84 14.22,38.84 L1.4
N8621808: length 3.1
  BOTTOM w1.27: R5.1 42.11,43.79 R4.2
N8621812: length 20.1
  BOTTOM w1.27: R6.1 36.45,28.88 35.36,29.97 35.36,43.31 R5.2
N8622846: length 11.2
  BOTTOM w0.508: R13.1 43.99,28.63 45.82,26.8 C11.1
  BOTTOM w0.762: R13.1 43.81,31.8 R12.2 ; U1.7 45.87,26.52 C11.1
N8622966: length 6.5
  BOTTOM w1.016: R10.2 38.3,32.13 R11.1
N8622970: length 5
  BOTTOM w1.016: R12.1 40.51,37.49 R11.2
N8625218: length 2.8
  BOTTOM w1.27: R3.1 21.97,17.37 R2.2
N8628411: length 4.4
  BOTTOM w1.27: 103.02,73.79 VR1.1 R25.1
N8629085: length 2.2
  BOTTOM w0.508: R30.2 139.9,42.77 U7.4
N8629124: length 9.7
  BOTTOM w1.27: D4.1 103.15,47.62 R27.2
N8637240: length 2.3
  BOTTOM w0.508: C35.1 155.6,43.18 R53.2
N8639668: length 3.2
  BOTTOM w1.27: R26.2 D3.1
N8650505: length 2.4
  BOTTOM w0.762: U2.3 139.62,48.26 R14.2
N8659234: length 5.9
  BOTTOM w0.508: R56.1 164.39,44.42 164.41,44.45 167.21,44.45 SW1.3
N8659238: length 17.9
  BOTTOM w0.508: U2.1 147.93,50.8 149.12,51.99 164.39,51.99 R56.2
N8678796: length 5.1
  BOTTOM w0.508: D5.1 116,20.88 C16.1 R28.2
N8704340: length 6.7
  BOTTOM w0.508: C22.2 R42.1 R41.1 183.11,38 Q2.1
N8715929: length 4.3
  BOTTOM w0.508: R40.1 R35.1 Q2.3
N8730428: length 29.3
  BOTTOM w0.381: 150.9,47.4 151.38,47.88 166.09,47.88 167.54,49.33 172.95,49.33 D9.2
  BOTTOM w0.508: U4.2 147.88,44.2 149.3,45.62 R33.1 149.96,46.46 150.9,47.4
N8731215: length 8
  BOTTOM w0.508: D9.1 176.28,49.86 176.78,49.35 176.78,44.68 177.48,43.98 178.85,43.98 R35.2
N8736247: length 12.9
  BOTTOM w0.508: R45.1 167.06,54.05 166.4,54.71 C31.1
  BOTTOM w0.762: C31.1 165.86,55.27 D13.1
N8746626: length 3.4
  BOTTOM w0.508: D12.2 158.8,59.61 C30.1
N8749328: length 30.6
  BOTTOM w0.508: R33.2 152.1,45.92 153.03,46.86 154.54,46.86 154.75,47.07 155.84,47.07 156.05,46.86 166.73,46.86 168.2,48.34 174.19,48.34 174.78,48.92 174.78,53.77 175.29,54.28 D10.2
N8758678: length 4.1
  BOTTOM w0.508: R38.1 183.54,48.95 R37.2
N8762816: length 2
  BOTTOM w0.508: U7.3 139.7,40.23 R31.1
N8800122: length 4.9
  BOTTOM w1.016: T2.6 153.06,55.22 D13.2
N8801044: length 2.6
  BOTTOM w0.508: C30.2 164.31,59.64 R49.2
N8807537: length 2.6
  BOTTOM w1.27: VR3.1 116.76,64.72 R48.1
N8808690: length 34.3
  TOP w1.016: v3(66.66,18.83) v3(66.66,37.33)
  BOTTOM w1.524: v3(66.66,18.83) 57.72,18.83 55.85,20.7 51.64,20.7 U1.13
N85759681: length 3
  BOTTOM w0.508: R34.2 C24.1
N87060550: length 3.2
  BOTTOM w0.508: R40.2 186.59,42.95 187.17,42.37 C22.1

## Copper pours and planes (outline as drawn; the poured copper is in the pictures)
+5VS on BOTTOM: 181.69,68.63 198.48,68.63 199.72,69.88 202.74,69.88 202.92,69.7 202.92,67.49 201.07,65.63 183.34,65.63 182.37,64.67 182.37,63.09 181.76,62.48 180.52,62.48 180.01,62.99 180.01,66.95
+5VS on BOTTOM: 170.87,42.04 170.87,42.09 171.83,43.05 171.88,43 171.88,42.04
VCCPR on BOTTOM: 51.26,32.94 53.64,32.94 53.82,32.77 53.82,31.75 53.67,31.6 51.28,31.6 50.98,31.9 50.98,32.66
VCCPR on BOTTOM: 131.93,46.66 131.93,48.23 131.24,48.92 131.24,49.1 131.52,49.38 132.97,49.38 133.17,49.17 133.17,46.69 133.15,46.66
B+ on BOTTOM: 113.31,29.92 115.52,29.92 115.77,29.67 115.77,29.29 115.42,28.93 115.42,27.03 114.91,26.52 114.1,26.52 113.54,27.08 113.54,28.85 113.21,29.18 113.21,29.82
B+ on BOTTOM: 30.99,47.52 33.76,47.52 33.76,44.17 33.05,43.46 33.05,26.04 36.4,22.68 38.58,22.68 39.27,22 39.27,20.35 41.15,18.47 52.37,18.47 54.08,16.76 58.44,16.76 58.97,16.23 59,16.23 60.43,14.81 99.24,14.81 102.54,18.11 102.54,25.1 101.09,26.54 101.09,27.15 100.91,27.33 100.91,28.32 100.97,28.37 106.22,28.37 106.71,27.89 106.71,26.85 105.33,25.48 105.33,15.77 101.19,11.63 56.03,11.63 50.8,16.87 50.8,16.89 40.31,16.89 31.37,25.83 31.37,44.22 30.99,44.6
RTN on BOTTOM: 98.4,6.02 99.82,6.02 102.01,3.84 114.33,3.84 116.54,6.05 116.54,11.68 117.02,12.17 120.04,12.17 120.32,11.89 120.32,5.33 121.82,3.84 123.32,3.84 125.6,6.12 125.6,11.35 126.16,11.91 127.56,11.91 128.02,11.46 128.02,4.55 128.73,3.84 129.95,3.84 133.4,7.29 134.7,7.29 135.38,6.6 135.38,5.51 131.62,1.75 100.46,1.75 97.84,4.37 97.84,5.46
RTN on BOTTOM: 135.03,45.64 135.03,44.27 134.72,43.97 134.54,43.97 133.65,44.86 134.44,45.64
RTN on BOTTOM: outline of 93 points within 38.44,17.53 138.13,84.25
RTN on BOTTOM: 135.51,41.05 135.51,40.87 135.97,40.41 136.58,40.41 136.58,39.17 136.55,39.14 135.94,39.14 135.51,38.71 135.33,38.71 135.28,38.76 135.28,40.82
RTN on BOTTOM: 119.2,32.36 120.6,32.36 120.57,32.33 120.57,23.83 120.42,23.67 119.58,23.67 118.24,25.02 118.24,31.34 119.2,32.31
RTN on BOTTOM: 112.37,40.77 113.31,39.83 117.98,39.83 118.14,39.67 118.14,39.45 118.03,39.34 118.03,39.24 118.16,39.12 119.71,39.12 119.72,39.13 120.75,38.1 120.75,37.34 120.78,37.31 120.24,36.78 119.33,36.78 118.75,37.36 118.75,38 118.29,38.46 116.13,38.46 115.95,38.63 113.49,38.63 112.52,39.6 109.98,39.6 109.04,38.66 108.38,38.66 107.92,39.12 107.92,39.7 108.99,40.77
VRECT on BOTTOM: 58.5,77.22 57.12,77.22 56.21,76.3 56.21,71.48 53.39,68.66 31.22,68.66 30.3,67.74 30.3,66.24 31.24,65.3 59.46,65.3 59.51,65.35 59.51,76.2
N8573798 on BOTTOM: 143,0.86 142.42,1.45 142.42,2.69 143.13,3.4 153.57,3.4 155.85,5.69 155.85,8.43 155.88,8.43 155.88,12.37 147.88,20.37 147.88,20.65 147.85,20.65 147.85,26.9 148.26,27.3 150.14,27.3 150.77,26.67 150.77,21.21 154.46,17.53 162.13,17.53 165.1,20.5 165.1,22.12 165.63,22.66 166.73,22.66 167.26,22.12 167.26,19.08 162.59,14.4 162.59,4.8 162.53,4.75 159.18,4.75 155.3,0.86
N8573798 on BOTTOM: 145.92,81.69 145.92,74.83 147.8,72.95 154.25,72.95 157,75.69 157,76.84 158.47,78.31 167.08,78.31 169.7,75.69 169.7,63.17 171.3,61.57 171.3,58.98 171.73,58.55 172.62,58.55 174.14,60.07 189.48,60.07 190.37,59.18 200.33,59.18 200.53,58.98 200.53,57.84 200.46,57.76 200.69,57.76 202.77,59.84 202.77,61.49 202.18,62.08 198.5,62.08 197.99,62.59 197.46,62.05 197.46,61.95 195.07,61.95 193.22,63.8 186.41,63.8 184.56,61.95 177.09,61.95 173.41,65.63 173.41,78.82 168.81,83.41 147.65,83.41
N8573798 on BOTTOM: 159.94,35.79 188.26,35.79 189.08,36.6 189.08,45.39 189.23,45.54 189.71,45.54 190.14,45.97 190.14,46.91 191.31,48.08 192.58,48.08 193.04,48.54 193.04,49.68 192.66,50.06 192.66,50.95 193.29,50.95 193.27,50.93 193.27,50.37 193.98,49.66 193.98,48.67 192.91,47.6 192.1,47.6 191.62,47.12 191.62,34.24 190.17,32.79 165.84,32.79 164.69,33.93 159.66,33.93 159.38,34.21 159.38,35.23
N8573822 on BOTTOM: 168.3,25.3 171.53,25.3 185.83,11 190.09,11 191.08,10.01 191.08,8.33 190.32,7.57 185.39,7.57 169.42,23.55 168.33,23.55 167.89,23.98 167.89,24.89
N8573908 on BOTTOM: 111.68,25.63 110.69,26.62 110.69,30.4 111.25,30.96 112.32,30.96 112.4,31.04 112.4,31.8 112.32,31.88 109.83,31.88 109.83,31.85 108.64,30.66 108.64,30.63 108.59,30.63 107.98,30.02 107.98,19 112.27,14.71 126.92,14.71 127.56,15.34 127.56,16.94 127.46,17.04 114.43,17.04 112.42,19.05 112.42,21.29 112.41,21.3 112.42,21.31 112.42,25.53 112.32,25.63
N8574082 on BOTTOM: 110.82,48.64 111.96,48.64 112.65,47.96 112.65,43.76 112.4,43.51 110.39,43.51 110.19,43.71 110.19,48.01
N8574082 on BOTTOM: 125.7,48.64 125.7,47.17 126.87,46 126.87,42.88 125.93,41.94 125.91,41.94 125.91,39.7 125.96,39.65 127.64,39.65 129.34,41.35 129.34,46.23 126.92,48.64
N8574090 on BOTTOM: 106.15,35.48 107.11,35.48 107.59,35 111.05,35 111.06,35.01 112.05,35.01 112.45,34.62 112.45,34.19 112.06,33.81 109.42,33.81 109.19,33.58 106.81,33.58 105.21,31.98 104.37,31.98 104.09,32.26 104.09,33.43
N8574122 on BOTTOM: 198.86,45.34 199.87,46.35 200.51,45.72 200.51,45.34 200.89,44.96 200.89,43.76 199.26,42.14 199.26,40.13 200.89,38.51 200.89,33.27 200.1,32.49 197,32.49 195.05,34.44 195.05,43.54 196.85,45.34
N8574170 on BOTTOM: 148.59,36.93 150.09,36.93 150.57,36.45 150.57,33.25 151.56,32.26 163.02,32.26 167.36,27.91 167.36,26.72 166.62,25.98 165.4,25.98 161.7,29.69 148.67,29.69 147.9,30.45 147.9,36.04 148.59,36.73
N8574324 on BOTTOM: 105.61,36.7 111.86,36.7 112.14,36.42 112.14,36.09 111.89,35.84 108.2,35.84 107.98,36.07 105.92,36.07 104.85,35 103.1,35 102.72,34.62 101.17,34.62 101.12,34.67 101.12,36.12 102.74,36.12 103.17,35.69 104.6,35.69
N8574348 on BOTTOM: 194.08,31.24 194.09,31.25 194.11,31.24 200.23,31.24 201.24,30.23 201.24,24.64 197.48,24.64 194.08,28.04 190.75,28.04 189.97,27.25 189.97,19.79 188.65,18.47 186.44,18.47 185.04,19.86 185.04,26.49 186.66,28.12 186.66,28.47 186.49,28.65 186.18,28.65 184.48,26.95 176.02,26.95 175.29,27.69 175.29,30.84 175.69,31.24
N8574438 on BOTTOM: 113.82,35.97 116.64,35.97 118.26,34.34 122.2,34.34 122.63,34.77 123.47,34.77 123.9,34.34 123.9,33.5 123.47,33.07 122.48,33.07 122.28,33.27 118.31,33.27 116.81,34.77 113.82,34.77 113.54,35.05 113.54,35.69
N8574666 on BOTTOM: 157.2,64.08 157.2,65.58 159.28,67.67 164.69,67.67 165.18,68.15 165.18,75.51 165.15,75.54 165.76,76.15 168.25,76.15 168.96,75.44 168.96,62.2 170.71,60.45 170.71,58.7 171.27,58.14 173,58.14 174.09,59.23 181.38,59.23 181.79,58.83 181.79,57.99 181.33,57.53 175.69,57.53 174.85,56.69 170.38,56.69 167.41,59.66 167.41,61.65 164.26,64.8 161.09,64.8 160.91,64.62 160.91,63.22 160.88,63.2 158.09,63.2
N8574858 on BOTTOM: 129.51,53.64 130.48,53.64 130.73,53.9 130.73,52.86 130.35,52.48 129.74,52.48 129.29,52.93 129.29,53.42
N8574878 on BOTTOM: 113.56,61.09 125.63,61.09 129.21,64.67 129.21,66.55 129.95,67.28 130.89,67.28 131.93,66.24 135.89,66.24 136.32,65.81 136.32,64.77 135.89,64.34 132.56,64.34 125.93,57.71 125.25,57.71 123.44,59.51 112.12,59.51 111.23,60.4 111.23,61.29 111.84,61.9 112.75,61.9
N8574990 on BOTTOM: 112.04,57.84 122.78,57.84 123.9,56.72 131.11,56.72 134.39,59.99 134.39,60.53 135.03,61.16 135.89,61.16 136.47,60.58 136.47,59.72 132.03,55.27 123.29,55.27 122.43,56.13 117.22,56.13 116.97,55.88 116.97,42.7 115.82,41.55 113.79,41.55 113.46,41.88 113.46,42.42 113.79,42.75 115.52,42.75 116.08,43.31 116.08,55.52 115.57,56.03 112.8,56.03 112.78,56.01 112.06,56.01 111.71,56.36 111.71,57.51
N8575976 on BOTTOM: 156.29,27.03 157.76,27.03 158.22,26.57 158.22,21.49 157.61,20.88 156.44,20.88 155.96,21.36 155.96,26.7
N8576150 on BOTTOM: 193.4,47.24 194.11,47.24 194.46,47.6 194.89,47.6 195.33,47.17 195.33,46.79 194.56,46.02 193.75,46.02 193.29,46.48 193.29,47.09 193.27,47.12
N8576938 on BOTTOM: 148.87,43 149.63,43 149.86,43.23 150.06,43.03 150.06,42.88 149.66,42.47 148.95,42.47 148.72,42.7 148.72,42.85
N8576942 on BOTTOM: 151.97,40.46 152.76,40.46 152.83,40.39 152.83,39.12 153.11,38.84 153.82,38.84 154.61,39.62 154.61,40.03 154.08,40.56 154.08,41.81 150.98,41.81 150.9,41.73 150.9,40.23 150.55,39.88 151,39.42 151.28,39.42 151.82,39.95 151.82,40.31
N8621032 on BOTTOM: 51.21,30.56 55.27,30.56 55.47,30.76 55.47,31.5 55.17,31.8 54.43,31.8 54.41,31.83 54.41,32.72 55.19,32.72 56.29,31.62 56.29,30.51 57.51,29.29 58.88,29.29 58.88,28.02 58.83,27.97 55.42,27.97 55.4,27.99 55.4,29.51 55.17,29.74 52.7,29.74 52.45,29.49 52.45,29.21 52.15,28.91 51.1,28.91 50.83,29.18 50.83,30.05 49.3,31.57 48.13,31.57 48.13,32.84 48.16,32.87 49.4,32.87 49.45,32.82 49.45,32.31
N8621040 on BOTTOM: 45.21,24.97 47.8,24.97 48.03,25.2 49.07,25.2 49.45,24.82 49.45,24.36 49.05,23.95 46.96,23.95 46.48,23.47 46.48,21.56 46.46,21.54 45.19,21.54 45.16,21.56 45.16,24.92
N8621068 on BOTTOM: 51.03,27.99 52.53,27.99 53.31,28.78 53.31,29.18 53.29,29.21 54.56,29.21 54.61,29.16 54.61,25.7 53.42,25.7 53.37,25.76 53.37,26.52 53.01,26.87 51.16,26.87 50.9,27.13 50.9,27.81 50.88,27.84
N8621110 on BOTTOM: 46.91,29.06 48.95,29.06 49.35,28.65 49.35,28.24 48.92,27.81 46.02,27.81 45.24,28.6 45.24,29.26 45.64,29.67 46.3,29.67
N8621154 on BOTTOM: 46.08,32.82 47.24,32.82 47.27,32.79 47.27,31.57 47.24,31.55 47.83,30.96 49.05,30.96 49.35,30.66 49.35,30.02 49.07,29.74 47.57,29.74 46,31.32 46,32.74
N8621246 on BOTTOM: 18.82,33.93 24,33.93 27.97,29.97 27.97,25.02 28.49,24.5 28.47,24.49 28.47,18.52 29.16,17.83 29.16,16.51 28.7,16.05 28.68,16.05 28.68,5.74 27.79,4.85 26.44,4.85 25.7,5.59 25.7,7.04 26.62,7.95 26.62,22.99 26.16,23.44 26.16,28.68 26.19,28.7 23.19,31.7 18.75,31.7 18.21,32.23 18.21,33.32
N8621358 on BOTTOM: 15.47,60.86 19.56,60.86 23.72,56.69 23.72,52.63 23.11,52.02 21.87,52.02 19.94,50.09 19.94,43.74 19.28,43.08 18.34,43.08 17.75,43.66 17.75,50.47 21.51,54.23 21.51,55.93 18.62,58.83 15.6,58.83 15.06,59.36 15.06,60.45
N8621482 on BOTTOM: 10.34,28.65 19.3,28.65 19.74,28.22 19.74,27.2 19.33,26.8 11.76,26.8 9.78,24.82 9.78,19.94 10.82,18.9 13.21,18.9 14,18.11 14,16.89 13.18,16.08 8.86,16.08 7.29,17.65 7.29,25.6
N8621528 on BOTTOM: 2.41,18.97 3.66,18.97 4.17,18.47 4.17,14.12 10.97,7.32 12.9,7.32 12.9,4.27 12.88,4.24 9.88,4.24 2.11,12.01 2.11,18.67
N8622000 on BOTTOM: 6.93,33.81 9.52,33.81 10.01,33.32 10.01,32.18 9.42,31.6 7.32,31.6 4.45,28.73 4.45,25.73 4.04,25.32 3.28,25.32 2.87,25.73 2.87,29.74
N8622846 on BOTTOM: 45.29,27.1 49.05,27.1 49.33,26.82 49.33,26.26 48.87,25.81 45.16,25.81 45.16,26.97
N8746626 on BOTTOM: 147.57,62.28 157.84,62.28 160.35,59.77 160.35,59.36 159.13,58.14 147.8,58.14 146.56,59.39 146.56,61.26
N8805084 on BOTTOM: 135.89,71.25 136.19,70.94 136.19,69.85 135.74,69.39 128.93,69.39 128.14,68.61 128.14,68.02 127.15,67.03 126.29,67.03 125.98,67.34 125.98,69.22 128.02,71.25
N8808690 on BOTTOM: 61.26,45.24 64.06,45.24 68.55,40.74 68.55,37.59 67.23,36.27 64.77,36.27 61.26,39.78

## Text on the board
Ref Des/Silkscreen Top: JP24 | TM | 1532 | S/N | DER-484 | REV A | JP3 | JP4 | JP22 | JP5 | JP13 | JP7 | JP6 | JP14 | JP8 | JP9 | JP20 | JP23 | JP21 | JP1 | JP15 | JP12 | JP10 | JP11 | JP16 | JP17 | JP19 | JP18 | +23V | RTN | HiperPFS-3 | HiperTFS-2
PAGE_OUTLINE: PLEASE DELETE THESE PINS | 13   MATERIAL FR4 COPPER 2oz THICKNESS 0.062" | SLOT OUTLINE
User.5: FIGURE | SIZE | 30.0 | 31.0 | 35.0 | 38.0 | 40.0 | 44.0 | 46.0 | 50.0 | 51.0 | 52.0 | 56.0 | 60.0 | 65.0 | 70.0 | 75.0 | 81.0 | 156.0 | DRILL CHART: TOP to BOTTOM | ALL UNITS ARE IN MILS | QTY | 32 | 2 | 28 | 8 | 55 | 12 | 4 | 22 | 18 | 9 | 7 | 5
